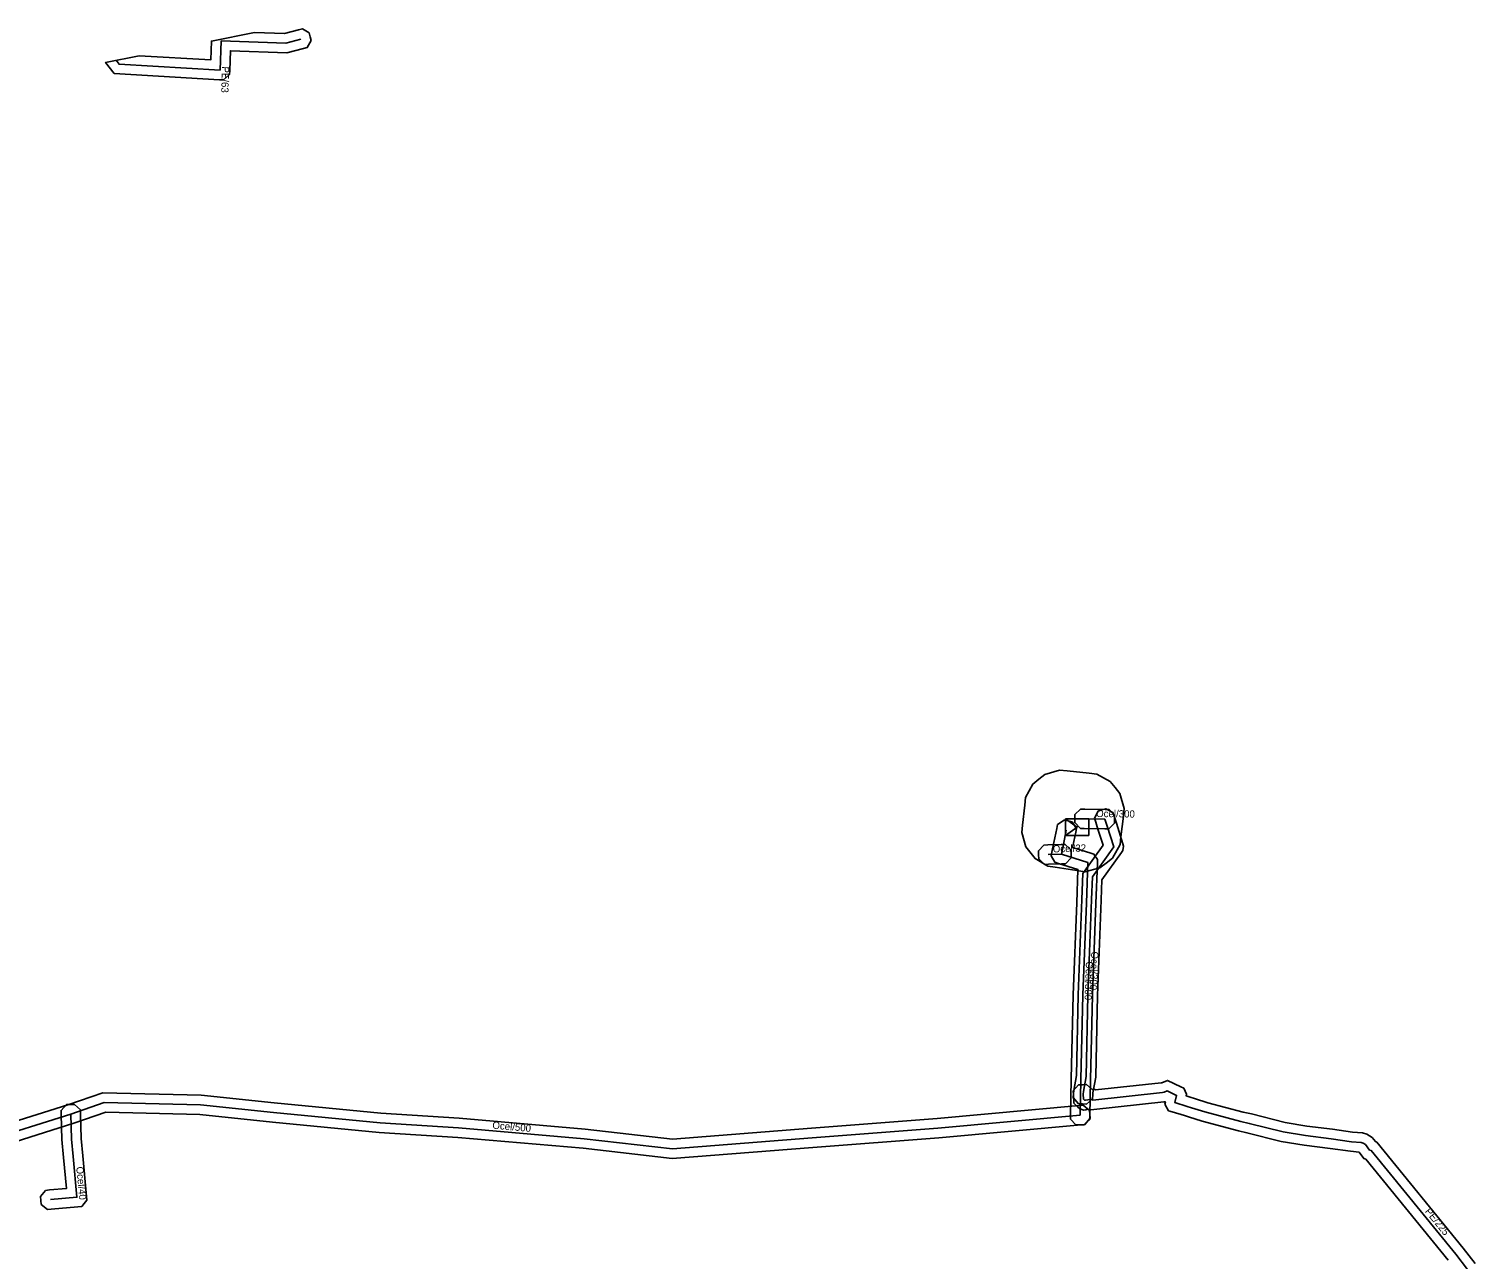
# Model space of a CAD drawing. Extents: x -760566 to -760255, y -976320 to -976047.
# Drawn here: x -760408.2 to -760258.3, y -976174.5 to -976046.9 of the extents above; entities that cross this region are included whole.
import ezdxf

# ---------------------------------------------------------------- set-up
doc = ezdxf.new("R2010")
doc.units = 0
for name, color, linetype in [('1', 7, 'Continuous'), ('14', 7, 'Continuous'), ('18', 7, 'Continuous'), ('20', 7, 'Continuous'), ('21', 7, 'Continuous'), ('24', 7, 'Continuous'), ('28', 7, 'Continuous'), ('3', 7, 'Continuous'), ('30', 7, 'Continuous')]:
    doc.layers.add(name, color=color, linetype=linetype)

# ---------------------------------------------------------------- blocks, each defined once
blk = doc.blocks.new('REG_STL')
at = {"layer": '21'}
for p, q in [((-1.22, 0.87), (1.22, 0.87)), ((1.22, 0.87), (1.22, -0.87)), ((1.22, -0.87), (-1.22, -0.87))]:
    blk.add_line(p, q, dxfattribs=at)
blk.add_lwpolyline([(-1.22, 0.87), (0, 0), (-1.22, -0.87)], close=True, dxfattribs=at)

msp = doc.modelspace()

# ---------------------------------------------------------------- linework, layer by layer
at = {"layer": '1'}
for points in [[(-760399.32, -976051.57), (-760400.23, -976050.42), (-760396.74, -976049.72), (-760389.32, -976050.15), (-760389.25, -976048.21), (-760384.78, -976047.31), (-760381.66, -976047.42), (-760380.22, -976047.05), (-760379.82, -976046.94), (-760379.11, -976047.36), (-760379, -976047.76), (-760378.9, -976048.16), (-760379.31, -976048.88), (-760379.71, -976048.98), (-760381.44, -976049.43), (-760387.29, -976049.21), (-760387.35, -976051.24), (-760387.37, -976051.66), (-760387.68, -976051.95), (-760387.99, -976052.23), (-760388.41, -976052.21)], [(-760297.4, -976147.18), (-760297.58, -976155.57), (-760297.58, -976155.59), (-760297.58, -976155.66), (-760297.87, -976157.26), (-760297.88, -976157.5), (-760297.91, -976157.91), (-760298.54, -976158.46), (-760298.95, -976158.43), (-760299.36, -976158.4), (-760299.91, -976157.77), (-760299.88, -976157.36), (-760299.85, -976157.02), (-760299.58, -976155.47), (-760299.4, -976147.12), (-760299.01, -976137.24), (-760299.01, -976137.2), (-760298.91, -976134.52), (-760296.82, -976131.59), (-760297.35, -976129.93), (-760297.58, -976129.2), (-760297.71, -976128.8), (-760297.33, -976128.06), (-760296.94, -976127.94), (-760296.54, -976127.81), (-760295.8, -976128.19), (-760295.68, -976128.58), (-760295.44, -976129.32), (-760294.76, -976131.46), (-760294.69, -976131.68), (-760294.76, -976132.15), (-760294.9, -976132.34), (-760296.93, -976135.2), (-760297.01, -976137.26), (-760297.02, -976137.3)], [(-760296.23, -976129.9), (-760296.65, -976129.89), (-760298.76, -976129.85), (-760299.17, -976129.85), (-760299.75, -976129.25), (-760299.74, -976128.84), (-760299.73, -976128.42), (-760299.14, -976127.85), (-760298.72, -976127.85), (-760296.61, -976127.89), (-760296.2, -976127.9), (-760295.62, -976128.49), (-760295.63, -976128.91), (-760295.64, -976129.32)], [(-760299.57, -976129.85), (-760299.65, -976130.25), (-760299.95, -976131.71), (-760299.98, -976131.84), (-760298.09, -976132.43), (-760297.77, -976132.53), (-760297.38, -976133.08), (-760297.39, -976133.42), (-760297.55, -976137.64), (-760297.91, -976147.16), (-760298.11, -976155.93), (-760298.11, -976155.96), (-760298.19, -976159.62), (-760298.2, -976160.04), (-760298.8, -976160.61), (-760299.21, -976160.6), (-760299.63, -976160.59), (-760300.2, -976159.99), (-760300.19, -976159.58), (-760300.11, -976155.9), (-760300.11, -976155.87), (-760299.91, -976147.1), (-760299.55, -976137.56), (-760299.42, -976134.11), (-760301.44, -976133.49), (-760301.8, -976133.37), (-760302.2, -976132.71), (-760302.12, -976132.33), (-760301.91, -976131.31), (-760301.61, -976129.85), (-760301.53, -976129.45), (-760300.84, -976128.99), (-760300.43, -976129.07), (-760300.03, -976129.16)], [(-760300.7, -976133.52), (-760301.11, -976133.53), (-760302.47, -976133.57), (-760302.89, -976133.58), (-760303.49, -976133.01), (-760303.5, -976132.6), (-760303.52, -976132.19), (-760302.95, -976131.58), (-760302.53, -976131.57), (-760301.17, -976131.53), (-760300.75, -976131.52), (-760300.15, -976132.09), (-760300.14, -976132.5), (-760300.13, -976132.92)], [(-760402.84, -976159.04), (-760402.83, -976159.45), (-760402.75, -976162.01), (-760402.59, -976163.8), (-760402.2, -976168.01), (-760402.17, -976168.42), (-760402.43, -976168.74), (-760402.7, -976169.06), (-760403.11, -976169.1), (-760405.85, -976169.35), (-760406.26, -976169.38), (-760406.9, -976168.85), (-760406.94, -976168.44), (-760406.97, -976168.03), (-760406.44, -976167.39), (-760406.03, -976167.35), (-760404.29, -976167.2), (-760404.58, -976163.98), (-760404.75, -976162.13), (-760404.83, -976159.51), (-760404.84, -976159.1), (-760404.28, -976158.49), (-760403.86, -976158.48), (-760403.45, -976158.47)]]:
    msp.add_lwpolyline(points, close=True, dxfattribs=at)
for points in [[(-760413.06, -976161.33), (-760404.14, -976158.53), (-760400.52, -976157.28), (-760390.33, -976157.51), (-760382.73, -976158.32), (-760371.69, -976159.38), (-760363.58, -976159.91), (-760350.52, -976161.04), (-760341.44, -976162.08), (-760327.05, -976160.94), (-760314.01, -976159.93), (-760299.28, -976158.6), (-760298.87, -976158.57), (-760298.23, -976159.1), (-760298.19, -976159.51), (-760298.16, -976159.92), (-760298.69, -976160.56), (-760299.1, -976160.6), (-760313.85, -976161.93), (-760326.89, -976162.94), (-760341.48, -976164.08), (-760350.72, -976163.03), (-760363.72, -976161.91), (-760371.85, -976161.38), (-760382.93, -976160.31), (-760390.45, -976159.51), (-760400.2, -976159.28), (-760403.52, -976160.43), (-760412.68, -976163.31)], [(-760261.03, -976174.64), (-760269.58, -976164.14), (-760269.79, -976164.08), (-760270.28, -976163.42), (-760271.17, -976163.34), (-760273.29, -976163.04), (-760275.98, -976162.7), (-760278.34, -976162.31), (-760281.9, -976161.41), (-760282.77, -976161.21), (-760286.53, -976160.22), (-760287.95, -976159.78), (-760288.39, -976159.64), (-760289.66, -976159.24), (-760290.03, -976159.13), (-760290.42, -976158.46), (-760290.36, -976158.2), (-760290.5, -976158.22), (-760297.77, -976159.01), (-760298.08, -976159.05), (-760298.2, -976158.98), (-760298.52, -976159.02), (-760298.61, -976159.03), (-760298.84, -976159.06), (-760299.27, -976158.91), (-760299.44, -976158.75), (-760299.83, -976158.36), (-760299.88, -976157.49), (-760299.9, -976157.08), (-760299.35, -976156.46), (-760298.94, -976156.43), (-760298.53, -976156.41), (-760297.93, -976156.93), (-760297.73, -976156.91), (-760297.59, -976156.98), (-760290.78, -976156.24), (-760290.74, -976156.23), (-760290.12, -976155.99), (-760288.77, -976156.64), (-760288.46, -976156.79), (-760288.15, -976157.41), (-760288.19, -976157.6), (-760287.79, -976157.73), (-760287.35, -976157.86), (-760285.97, -976158.3), (-760282.29, -976159.27), (-760281.43, -976159.47), (-760277.94, -976160.35), (-760275.7, -976160.72), (-760273.03, -976161.06), (-760270.95, -976161.36), (-760269.91, -976161.44), (-760269.46, -976161.55), (-760268.92, -976161.9), (-760268.59, -976162.34), (-760268.44, -976162.38), (-760259.47, -976173.4), (-760258.25, -976174.97)]]:
    msp.add_lwpolyline(points, dxfattribs=at)
at = {"layer": '14'}
for points in [[(-760379.97, -976048.01), (-760381.55, -976048.43), (-760388.25, -976048.18), (-760388.35, -976051.21), (-760398.82, -976050.6), (-760399.13, -976050.2)], [(-760300.63, -976130.05), (-760300.93, -976131.51), (-760301.14, -976132.53), (-760298.39, -976133.39), (-760298.55, -976137.6), (-760298.91, -976147.13), (-760299.11, -976155.9), (-760299.11, -976155.93), (-760299.19, -976159.6)], [(-760421.05, -976163.15), (-760419.8, -976163.01), (-760415.11, -976162.5), (-760412.87, -976162.32), (-760403.83, -976159.48), (-760400.36, -976158.28), (-760390.39, -976158.51), (-760382.83, -976159.31), (-760371.77, -976160.38), (-760363.65, -976160.91), (-760350.62, -976162.03), (-760341.46, -976163.08), (-760326.97, -976161.94), (-760313.93, -976160.93), (-760299.19, -976159.6)], [(-760403.83, -976159.48), (-760403.75, -976162.07), (-760403.58, -976163.89), (-760403.2, -976168.1), (-760405.94, -976168.35)]]:
    msp.add_lwpolyline(points, dxfattribs=at)
at = {"layer": '18'}
msp.add_lwpolyline([(-760301.14, -976132.53), (-760302.5, -976132.57)], dxfattribs=at)
at = {"layer": '24'}
for points in [[(-760296.63, -976128.89), (-760296.4, -976129.62), (-760295.71, -976131.76), (-760297.92, -976134.86), (-760298.01, -976137.23), (-760298.01, -976137.27), (-760298.4, -976147.15), (-760298.58, -976155.57), (-760298.58, -976155.57), (-760298.86, -976157.14), (-760298.88, -976157.43)], [(-760259.04, -976175.59), (-760260.25, -976174.02), (-760269.01, -976163.26), (-760269.19, -976163.21), (-760269.61, -976162.64), (-760269.86, -976162.48), (-760270.07, -976162.43), (-760271.06, -976162.35), (-760273.16, -976162.05), (-760275.84, -976161.71), (-760278.14, -976161.33), (-760281.66, -976160.44), (-760282.53, -976160.24), (-760286.25, -976159.26), (-760287.65, -976158.82), (-760288.09, -976158.68), (-760289.36, -976158.29), (-760289.2, -976157.54), (-760290.16, -976157.08), (-760290.47, -976157.2), (-760290.64, -976157.23), (-760297.88, -976158.02), (-760297.92, -976157.94), (-760298.64, -976158.03), (-760298.73, -976158.04), (-760298.85, -976157.92), (-760298.88, -976157.43)]]:
    msp.add_lwpolyline(points, dxfattribs=at)
at = {"layer": '28'}
msp.add_lwpolyline([(-760296.63, -976128.89), (-760298.74, -976128.85)], dxfattribs=at)
at = {"layer": '3'}
msp.add_lwpolyline([(-760294.62, -976127.78), (-760294.71, -976128.57), (-760294.96, -976130.72), (-760295.05, -976131.53), (-760295.85, -976132.95), (-760296.5, -976133.45), (-760297.15, -976133.94), (-760298.72, -976134.35), (-760299.53, -976134.23), (-760301.77, -976133.89), (-760302.54, -976133.78), (-760303.87, -976132.99), (-760304.82, -976131.77), (-760305.24, -976130.28), (-760305.16, -976129.51), (-760304.94, -976127.45), (-760304.85, -976126.65), (-760304.09, -976125.26), (-760303.47, -976124.76), (-760302.85, -976124.26), (-760301.32, -976123.81), (-760300.53, -976123.9), (-760298.26, -976124.14), (-760297.47, -976124.23), (-760296.07, -976124.99), (-760295.57, -976125.62), (-760295.07, -976126.24)], close=True, dxfattribs=at)

# ---------------------------------------------------------------- block references
at = {"layer": '21'}
msp.add_blockref('REG_STL', (-760299.5, -976129.72), dxfattribs=at)

# ---------------------------------------------------------------- texts
at = {"layer": '20'}
for s, rotation, p in [('PE/63', 268.1299, (-760388.15, -976050.82)), ('Ocel/32', 1.6366, (-760302.02, -976132.35)), ('Ocel/300', 267.8311, (-760298.59, -976143.64)), ('Ocel/500', 355.0872, (-760360.15, -976160.99)), ('Ocel/40', 275.2153, (-760403.27, -976164.96))]:
    msp.add_text(s, height=0.75, rotation=rotation, dxfattribs=at).set_placement(p)
at = {"layer": '30'}
for s, rotation, p in [('Ocel/300', 359.0501, (-760297.54, -976128.67)), ('Ocel/300', 267.7627, (-760298.03, -976142.6)), ('PE/225', 309.1499, (-760263.49, -976169.59))]:
    msp.add_text(s, height=0.75, rotation=rotation, dxfattribs=at).set_placement(p)

doc.saveas('drawing.dxf')
